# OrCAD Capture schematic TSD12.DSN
size A; title: TSDxx Unidirectional Protection Diodes in SOD-323; rev: 1.0; note: Datasheet: SLVSH43
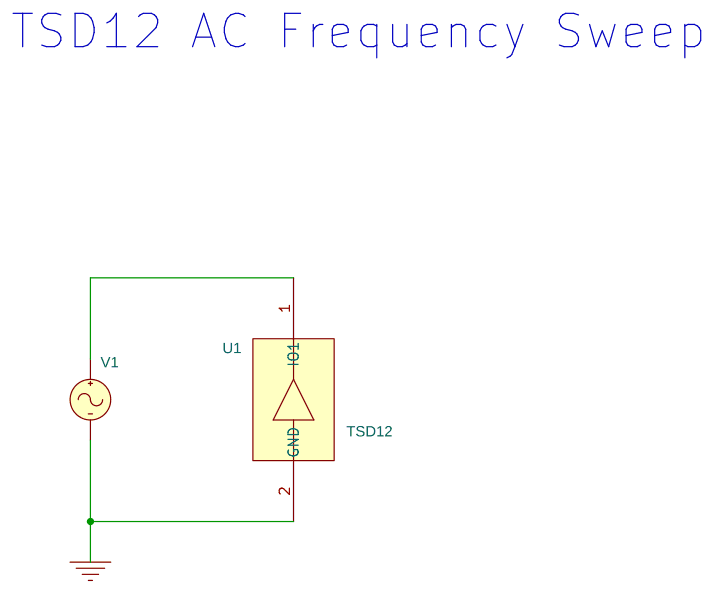
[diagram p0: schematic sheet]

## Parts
U1  TSD12
V1  VAC

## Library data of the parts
U1 = TSD12
V1 = VAC

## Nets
0: U1.2(GND) V1.2(-)
N02937: U1.1(IO1) V1.1(+)

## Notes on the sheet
- TSD12 AC Frequency Sweep
